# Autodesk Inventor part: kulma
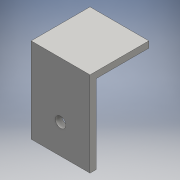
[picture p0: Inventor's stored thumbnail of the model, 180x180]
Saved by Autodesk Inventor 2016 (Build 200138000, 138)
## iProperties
Created: 2016-02
Part Number: kulma
Material: Generic
Document SubType Name: Modeling
Designer: Juha-Pekka
Density: 1 g/cm^3
Appearance: Default
Author: Juha-Pekka
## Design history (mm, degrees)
sketch "Sketch1"
  geometry: L1 (0, 0)-(56, 0); L2 (56, 0)-(56, -75); L3 (56, -75)-(0, -75); L4 (0, -75)-(0, 0)
  constraints: 8 end point, 2 parallel, 1 horizontal, 1 perpendicular
  dimensions: "d0" = 56 distance of L2.end L3.end; "d1" = 75 distance of L1.end L2.end
extrude "Extrusion1" new body sketch "Sketch1" distance "d2" = 6; taper "d3" = 0 deg
sketch "Sketch2"
  geometry: L1 (0, 0)-(56, 0); L2 (56, 0)-(56, 56); L3 (56, 56)-(0, 56); L4 (0, 56)-(0, 0); 1 further point
  constraints: 8 end point, 2 parallel, 1 horizontal, 1 perpendicular
  dimensions: "d4" = 56 distance of L3.end L2.end; "d5" = 56 distance of L2.end L1.end
extrude "Extrusion2" join sketch "Sketch2" distance "d6" = 6; taper "d7" = 0 deg
sketch "Sketch3"
  geometry: L1 (0, -75)-(-56, -75) reference; L2 (0, -75)-(0, -19); L3 (0, 0)-(0, -75) reference; L4 (0, -19)-(-56, -19); L5 (-56, -75)-(-56, 0) reference; L6 (-56, -75)-(0, -75); L7 (-56, -75)-(0, -19); L8 (0, -75)-(-56, -19); C1 r 6.406 at (-28, -47)
  constraints: 10 end point, 2 point on line, 1 centre point, 1 collinear, 1 midpoint, 1 perpendicular
  dimensions: "d8" = 56 distance of L1.start L2.end
hole "Hole1" sketch "Sketch3" at (-28, -47) diameter "d9" = 10; stored, may be unused: countersink angle "d13" = 90 deg, drill point angle "d15" = 118 deg; dims "d10" = 6, "d11" = 4, "d12" = 2, "d14" = 8
body "Solid1"
